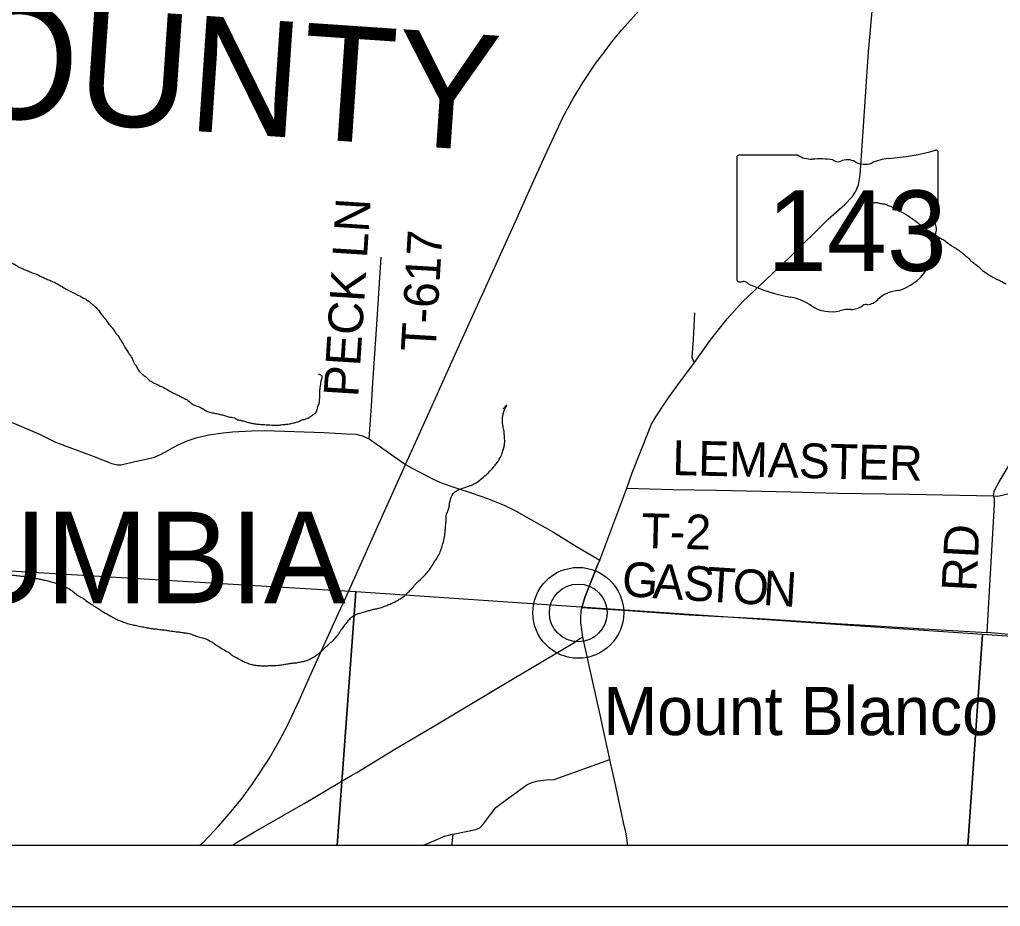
# Model space of a CAD drawing. Extents: x -8.2 to 34, y 0 to 22.
# Drawn here: x 5.685 to 7.291, y 14 to 15.452 of the extents above; entities that cross this region are included whole.
import ezdxf

# ---------------------------------------------------------------- set-up
doc = ezdxf.new("R2010")
doc.units = 0
for name, color, linetype in [('GM_X_Corporation', 7, 'Continuous'), ('GM_X_County_Road', 7, 'Continuous'), ('GM_X_County_Text', 7, 'Continuous'), ('GM_X_Minor_River', 7, 'Continuous'), ('GM_X_State_Location', 7, 'Continuous'), ('GM_X_State_Route', 7, 'Continuous'), ('GM_X_State_Shield', 7, 'Continuous'), ('GM_X_Township_Road', 7, 'Continuous'), ('GM_X_Township_Road_Text', 7, 'Continuous'), ('GM_X_Township_Text', 7, 'Continuous'), ('GM_X_Unincorporated', 7, 'Continuous'), ('GM_X_Unincorporated_Location', 7, 'Continuous'), ('GM_X_Unincorporated_Text', 7, 'Continuous'), ('SH_Data', 7, 'Continuous')]:
    doc.layers.add(name, color=color, linetype=linetype)

msp = doc.modelspace()

# ---------------------------------------------------------------- linework, layer by layer
at = {"layer": 'GM_X_Corporation'}
for points in [[(4.1481, 14.1), (8.9, 14.1), (8.9, 15.3663), (8.5054, 15.392), (7.8479, 15.4343), (7.082, 15.4841), (6.7558, 15.5053), (6.7389, 15.5064), (6.2987, 15.5287), (5.4088, 15.5882), (4.4836, 15.6492), (4.4152, 15.6505), (4.2922, 15.6569), (4.2674, 15.658), (4.2558, 15.6585), (4.2352, 15.4906), (4.2113, 15.0848), (4.1846, 14.6878), (4.1741, 14.5315), (4.1604, 14.3288)], [(5.1819, 14.1), (6.2054, 14.1), (6.2355, 14.5152), (5.2132, 14.576)], [(6.2054, 14.1), (7.2372, 14.1), (7.2616, 14.4454), (6.2355, 14.5152)], [(7.2372, 14.1), (8.2568, 14.1), (8.2775, 14.3753), (7.2616, 14.4454)]]:
    msp.add_lwpolyline(points, close=True, dxfattribs=at)
at = {"layer": 'GM_X_County_Road'}
for points in [[(6.07, 14.1219), (6.1511, 14.1686), (6.2289, 14.2147), (6.2374, 14.2194), (6.2996, 14.2572), (6.3617, 14.2938), (6.4745, 14.3616), (6.5914, 14.4312), (6.6022, 14.4388), (6.6074, 14.4407)], [(6.0341, 14.1), (6.0414, 14.1052), (6.0562, 14.1139), (6.07, 14.1219)]]:
    msp.add_lwpolyline(points, dxfattribs=at)
at = {"layer": 'GM_X_Minor_River'}
for points in [[(5.3703, 15.4396), (5.3769, 15.4348), (5.3824, 15.4281), (5.3879, 15.4211), (5.394, 15.4122), (5.398, 15.406), (5.4004, 15.399), (5.4032, 15.3913), (5.4052, 15.3841), (5.4062, 15.3772), (5.4088, 15.3649), (5.4108, 15.3573), (5.414, 15.3503), (5.4172, 15.3445), (5.4222, 15.3356), (5.4281, 15.3286), (5.4344, 15.3242), (5.4399, 15.3202), (5.4462, 15.3139), (5.4517, 15.3092), (5.4598, 15.3017), (5.4657, 15.2962), (5.4727, 15.2891), (5.4778, 15.2833), (5.4826, 15.277), (5.4873, 15.27), (5.4934, 15.26), (5.4977, 15.253), (5.5009, 15.2472), (5.5041, 15.2398), (5.5091, 15.2309), (5.5135, 15.2243), (5.52, 15.2158), (5.5236, 15.2096), (5.5291, 15.2033), (5.5357, 15.1974), (5.542, 15.1919), (5.5475, 15.1875), (5.5587, 15.1795), (5.5668, 15.1743), (5.5746, 15.168), (5.582, 15.1632), (5.5899, 15.1591), (5.5965, 15.1536), (5.6043, 15.1469), (5.6102, 15.1417), (5.6165, 15.137), (5.6234, 15.1299), (5.6293, 15.1236), (5.6344, 15.1178), (5.6373, 15.1116), (5.6374, 15.1047), (5.638, 15.099), (5.6443, 15.0844), (5.6487, 15.0774), (5.6515, 15.0712), (5.6555, 15.065), (5.6613, 15.0595), (5.6703, 15.0546), (5.677, 15.0514), (5.6833, 15.0474), (5.6931, 15.0429), (5.6987, 15.0408), (5.7058, 15.0375), (5.7133, 15.035), (5.7211, 15.0309), (5.7275, 15.0281), (5.7346, 15.0252), (5.7421, 15.0219), (5.7496, 15.0178), (5.7577, 15.013), (5.7659, 15.0085), (5.7745, 15.0041), (5.7809, 15.0008), (5.7865, 14.998), (5.7936, 14.994), (5.7991, 14.9904), (5.8061, 14.9844), (5.812, 14.9789), (5.8215, 14.9664), (5.8284, 14.9582), (5.8328, 14.952), (5.8386, 14.945), (5.8426, 14.9391), (5.847, 14.9333), (5.852, 14.9255), (5.8556, 14.9197), (5.8592, 14.9131), (5.8635, 14.9062), (5.8686, 14.8988), (5.8714, 14.8926), (5.8761, 14.8845), (5.88, 14.8779), (5.8859, 14.8716), (5.8918, 14.8669), (5.8988, 14.8606)], [(7.0807, 15.1515), (7.0868, 15.1524), (7.0944, 15.151), (7.1023, 15.1496), (7.1087, 15.1471), (7.1158, 15.1442), (7.1221, 15.1398), (7.1303, 15.1361), (7.137, 15.1325), (7.1452, 15.1269), (7.1522, 15.1217), (7.1626, 15.1138), (7.1715, 15.1074), (7.1801, 15.1022), (7.1882, 15.097), (7.1953, 15.0926), (7.2016, 15.0886), (7.2094, 15.0826), (7.2154, 15.079), (7.2213, 15.075), (7.2287, 15.0695), (7.2354, 15.0639), (7.2423, 15.0572), (7.249, 15.0521), (7.2546, 15.0477), (7.2616, 15.0414), (7.2679, 15.0366), (7.2746, 15.0326), (7.2824, 15.0278), (7.2884, 15.0253), (7.2943, 15.0221), (7.3003, 15.0188)], [(5.8988, 14.8606), (5.9059, 14.8569), (5.9156, 14.852), (5.9238, 14.8479), (5.9324, 14.8431), (5.9403, 14.839), (5.9459, 14.8362), (5.9533, 14.8325), (5.9608, 14.8285), (5.9663, 14.8237), (5.9742, 14.8197), (5.9809, 14.8172), (5.9865, 14.814), (5.9928, 14.8103), (6.0004, 14.8082), (6.006, 14.8072), (6.0143, 14.8054), (6.0207, 14.8037), (6.0271, 14.8016), (6.0369, 14.7998), (6.0425, 14.7969), (6.0481, 14.7956), (6.0542, 14.7939), (6.0613, 14.7921), (6.0673, 14.7908), (6.0734, 14.7898), (6.0825, 14.7891), (6.0912, 14.7885), (6.1067, 14.7879), (6.1136, 14.7885), (6.1212, 14.7894), (6.1281, 14.7903), (6.1353, 14.7919), (6.1422, 14.794), (6.148, 14.7965), (6.1541, 14.7981), (6.1603, 14.8014), (6.1661, 14.8053), (6.1716, 14.8109), (6.173, 14.8165), (6.1755, 14.8233), (6.1764, 14.8289), (6.1769, 14.8445), (6.1775, 14.8502), (6.1785, 14.8562), (6.1794, 14.8619), (6.1804, 14.8679), (6.1744, 14.8712)], [(6.4774, 14.7821), (6.4761, 14.789), (6.4756, 14.7951), (6.4758, 14.8008), (6.4771, 14.8064), (6.4792, 14.8136), (6.4829, 14.8203), (6.4766, 14.8148)], [(5.924, 14.4525), (5.9308, 14.4512), (5.9418, 14.4497), (5.9478, 14.4491), (5.9546, 14.4481), (5.9629, 14.4467), (5.9708, 14.4441), (5.9783, 14.4412), (5.9866, 14.4391), (5.9941, 14.4362), (6.0067, 14.4281), (6.0138, 14.4237), (6.022, 14.4189), (6.0287, 14.4149), (6.0346, 14.4105), (6.0413, 14.4069), (6.0506, 14.4016), (6.0574, 14.3987), (6.0649, 14.3962), (6.0705, 14.3949), (6.077, 14.3943), (6.083, 14.3937), (6.0895, 14.3939), (6.0971, 14.3944), (6.1081, 14.3948), (6.1176, 14.396), (6.1249, 14.3973), (6.131, 14.3982), (6.1367, 14.3988), (6.1443, 14.4), (6.1516, 14.4017), (6.1581, 14.4038), (6.1662, 14.408), (6.1736, 14.4131), (6.1795, 14.4182), (6.1873, 14.4256), (6.1944, 14.4318), (6.2014, 14.4384), (6.2074, 14.4462), (6.2113, 14.4518), (6.2161, 14.458), (6.2209, 14.4647), (6.2256, 14.4703), (6.2323, 14.4761), (6.2384, 14.479), (6.2461, 14.4814), (6.2534, 14.4834), (6.2595, 14.4851), (6.2664, 14.4868), (6.2729, 14.4881), (6.2829, 14.4915), (6.2898, 14.4943), (6.2971, 14.4975), (6.3037, 14.5011), (6.3099, 14.5047), (6.3169, 14.5102), (6.3228, 14.5157), (6.3283, 14.5216), (6.3346, 14.5286), (6.3436, 14.5374), (6.3495, 14.5433), (6.3551, 14.5499), (6.3606, 14.5581), (6.3666, 14.5674), (6.3719, 14.5763), (6.3756, 14.5853), (6.3782, 14.594), (6.3808, 14.6049), (6.3818, 14.6121), (6.3824, 14.6197), (6.383, 14.6269), (6.3837, 14.6337), (6.3835, 14.6401), (6.3856, 14.6458), (6.388, 14.6518), (6.389, 14.6586), (6.3904, 14.6654), (6.3925, 14.671), (6.3973, 14.6784), (6.4035, 14.682), (6.4127, 14.6855), (6.4204, 14.6879), (6.4265, 14.6904), (6.4343, 14.6947), (6.4425, 14.7012), (6.4511, 14.7085), (6.4569, 14.7144), (6.4637, 14.7226), (6.468, 14.7281), (6.4712, 14.7337), (6.4753, 14.7419), (6.4775, 14.7494), (6.4788, 14.7555), (6.4794, 14.7615), (6.4789, 14.7692), (6.4784, 14.7764), (6.4774, 14.7821)], [(5.1466, 14.5717), (5.1609, 14.5766), (5.1712, 14.577), (5.1807, 14.5774), (5.1872, 14.578), (5.1944, 14.5774), (5.2015, 14.5752), (5.2083, 14.5727), (5.2183, 14.5675), (5.2277, 14.5622), (5.2381, 14.5581), (5.2592, 14.5528), (5.269, 14.551), (5.2769, 14.5488), (5.2905, 14.5453), (5.298, 14.5435), (5.3078, 14.5417), (5.3154, 14.5399), (5.3236, 14.5374), (5.3319, 14.5352), (5.3394, 14.5331), (5.3481, 14.5305), (5.356, 14.5291), (5.3635, 14.5273), (5.3722, 14.5248), (5.3816, 14.5222), (5.3895, 14.5204), (5.397, 14.519), (5.4031, 14.518), (5.4133, 14.5166), (5.422, 14.5155), (5.4337, 14.5147), (5.4405, 14.5145), (5.4489, 14.5154), (5.4558, 14.5163), (5.4615, 14.5172), (5.4676, 14.5189), (5.4738, 14.5203), (5.4803, 14.5216), (5.4867, 14.5225), (5.4944, 14.5241), (5.5017, 14.5265), (5.5089, 14.5278), (5.5162, 14.5295), (5.5246, 14.5307), (5.533, 14.5312), (5.5421, 14.5309), (5.55, 14.5303), (5.5587, 14.5296), (5.569, 14.5296), (5.5789, 14.5304), (5.5892, 14.532), (5.5999, 14.5335), (5.6082, 14.5348), (5.6174, 14.5364), (5.63, 14.539), (5.6357, 14.54), (5.6449, 14.5415), (5.6544, 14.5424), (5.6628, 14.5432), (5.6704, 14.5426), (5.6791, 14.5419), (5.6878, 14.5409), (5.6938, 14.5403), (5.7006, 14.5393), (5.7063, 14.5384), (5.7127, 14.537), (5.7199, 14.5356), (5.7274, 14.5339), (5.7353, 14.5321), (5.7432, 14.5296), (5.7492, 14.5278), (5.7556, 14.5253), (5.7623, 14.5221), (5.7679, 14.5189), (5.7735, 14.5149), (5.7801, 14.5097), (5.7876, 14.5053), (5.7961, 14.4993), (5.8024, 14.4949), (5.8106, 14.4897), (5.8173, 14.4853), (5.8236, 14.4813), (5.8311, 14.4773), (5.8374, 14.4736), (5.8434, 14.4704), (5.8505, 14.4675), (5.8569, 14.465), (5.8666, 14.462), (5.8745, 14.4603), (5.8836, 14.4584), (5.8923, 14.4566), (5.9002, 14.4552), (5.9081, 14.4542), (5.9164, 14.4532), (5.924, 14.4525)]]:
    msp.add_spline(points, degree=3, dxfattribs=at)
at = {"layer": 'GM_X_State_Route'}
for points in [[(6.7476, 14.8327), (6.7629, 14.8542), (6.7898, 14.8906), (6.8166, 14.9279), (6.8432, 14.962), (6.8591, 14.9796), (6.8687, 14.9899), (6.9461, 15.0632), (7.0087, 15.1252), (7.0358, 15.1494), (7.0486, 15.1622), (7.0541, 15.1711), (7.0585, 15.1816), (7.0614, 15.1979), (7.0661, 15.269), (7.075, 15.3989), (7.0822, 15.4836)], [(5.9804, 14.1), (5.9868, 14.1059), (6.0116, 14.1319), (6.0284, 14.1515), (6.0478, 14.1752), (6.0665, 14.2006), (6.0945, 14.2428), (6.1109, 14.2714), (6.1231, 14.2951), (6.1436, 14.3382), (6.1599, 14.3752), (6.2073, 14.4799), (6.2193, 14.5057), (6.2529, 14.581), (6.2781, 14.637), (6.317, 14.7235), (6.3386, 14.7713), (6.4078, 14.9242), (6.4654, 15.0514), (6.4725, 15.0671), (6.497, 15.1215), (6.5242, 15.1825), (6.5487, 15.2367), (6.5758, 15.2938), (6.5915, 15.3226), (6.6079, 15.3497), (6.6281, 15.3803), (6.643, 15.3999), (6.6546, 15.4154), (6.671, 15.4354), (6.7039, 15.472)], [(6.6348, 14.5669), (6.6615, 14.6369), (6.679, 14.685), (6.6879, 14.71), (6.7154, 14.7784), (6.7197, 14.7893), (6.7267, 14.8015), (6.7424, 14.8253), (6.7476, 14.8327)], [(6.6057, 14.4896), (6.6111, 14.5072), (6.6325, 14.5615), (6.6348, 14.5669)], [(6.6801, 14.1), (6.6797, 14.1092), (6.6778, 14.1213), (6.6738, 14.1372), (6.6611, 14.1967), (6.6515, 14.2403), (6.6354, 14.3134), (6.6166, 14.3991), (6.6074, 14.4407), (6.6057, 14.4528), (6.6041, 14.465), (6.6041, 14.4748), (6.6043, 14.4822), (6.6057, 14.4896)]]:
    msp.add_lwpolyline(points, dxfattribs=at)
at = {"layer": 'GM_X_State_Shield'}
for p, q in [((7.1888, 15.1301), (7.1888, 15.2347)), ((6.8592, 15.2263), (6.8592, 15.0262)), ((6.959, 15.2298), (6.8625, 15.2298)), ((7.1888, 15.1301), (7.1888, 15.1301))]:
    msp.add_line(p, q, dxfattribs=at)
for centre, major_axis, start_param, end_param in [((7.0714, 15.5026), (0.3495, 0), 4.814394, 5.042369), ((7.1851, 15.2352), (0.00367, 0), 6.141152, 7.989035), ((6.863, 15.2268), (0.00382, 0), 1.712693, 3.28349), ((6.982, 15.253), (0.037, 0), 4.042523, 4.731795), ((6.9942, 15.1174), (0.133, 0), 1.404758, 1.657858), ((7.0244, 15.2278), (0.0107, 0), 3.836095, 5.185415), ((7.0401, 15.2047), (0.0222, 0), 0.950623, 2.079405), ((7.0688, 15.2364), (0.0267, 0), 4.081561, 5.145723), ((7.116, 15.1687), (0.0703, 0), 1.699011, 2.107814), ((7.188, 15.1224), (0.00568, 0), 1.883978, 3.671073), ((7.1849, 15.1297), (0.00393, 0), 5.05454, 6.418171), ((7.1518, 15.1091), (0.0341, 0), 5.934695, 6.695948), ((7.2019, 15.0862), (0.0248, 0), 2.387724, 3.262537), ((7.091, 15.0729), (0.0874, 0), 5.101752, 6.440018), ((6.863, 15.0258), (0.00385, 0), 3.00124, 4.508301), ((6.8636, 15.0463), (0.0294, 0), 4.665946, 4.897461), ((6.8696, 15.0147), (0.0106, 0), 0.519207, 1.627899), ((7.0034, 15.1945), (0.2524, 0), 4.195997, 4.488961), ((6.9282, 14.9363), (0.079, 0), 0.823519, 1.323587), ((7.0672, 15.0068), (0.0282, 0), 4.937069, 5.64225), ((7.1278, 14.97), (0.0479, 0), 1.647645, 2.488434), ((7.0136, 15.0137), (0.0501, 0), 4.026481, 4.996735), ((7.0426, 14.9445), (0.0412, 0), 1.495662, 1.94098), ((7.0462, 14.9987), (0.0267, 0), 4.691044, 5.507374), ((7.0704, 14.9793), (0.00752, 0), 1.147584, 2.315152)]:
    msp.add_ellipse(centre, major_axis=major_axis, ratio=0.8, start_param=start_param, end_param=end_param, dxfattribs=at)
at = {"layer": 'GM_X_Township_Road'}
msp.add_line((6.2573, 14.7654), (6.317, 14.7235), dxfattribs=at)
for points in [[(6.2573, 14.7654), (6.2616, 14.8192), (6.2637, 14.8573), (6.2702, 14.9529), (6.2769, 15.063)], [(6.7898, 14.8906), (6.7875, 14.8952), (6.7862, 14.8994), (6.7885, 14.9284), (6.7908, 14.9717)], [(5.6733, 14.7925), (5.7182, 14.7732), (5.744, 14.7598), (5.8058, 14.7371), (5.8364, 14.7249), (5.8454, 14.7231), (5.8516, 14.7229), (5.874, 14.7285), (5.8927, 14.732), (5.906, 14.7354), (5.9173, 14.7406), (5.9436, 14.7551), (5.9597, 14.762), (5.9759, 14.7677), (5.9953, 14.7719), (6.0187, 14.7755), (6.034, 14.7768), (6.0649, 14.7785), (6.0864, 14.7793), (6.1837, 14.7758), (6.2197, 14.7739), (6.236, 14.7729), (6.2419, 14.7717), (6.2464, 14.7705), (6.2501, 14.7688), (6.2573, 14.7654)], [(7.2792, 14.6724), (7.2862, 14.6714), (7.3117, 14.6775), (7.3412, 14.6846), (7.3507, 14.687), (7.3594, 14.6876), (7.3791, 14.6862), (7.3894, 14.686), (7.3967, 14.6864), (7.404, 14.6882), (7.4099, 14.691), (7.4202, 14.6961), (7.4479, 14.7122), (7.4852, 14.7337), (7.4989, 14.7425), (7.5078, 14.7465), (7.5172, 14.7494)], [(6.317, 14.7235), (6.328, 14.7177), (6.3624, 14.6995), (6.377, 14.6931), (6.3996, 14.6852), (6.426, 14.6763), (6.451, 14.6679), (6.4782, 14.6567), (6.5001, 14.646), (6.522, 14.6336), (6.5592, 14.6125), (6.5968, 14.5892), (6.6348, 14.5669)], [(7.2792, 14.6724), (7.2809, 14.6807), (7.2885, 14.6953), (7.3105, 14.7317)], [(6.6057, 14.4896), (6.6817, 14.4844), (6.7812, 14.4775), (6.8968, 14.4712), (7.022, 14.4633), (7.0692, 14.4604), (7.1653, 14.4542), (7.2692, 14.4482), (7.2741, 14.5354), (7.2812, 14.6579), (7.2812, 14.6671), (7.2792, 14.6724)], [(6.679, 14.685), (6.7547, 14.6828), (6.8261, 14.6816), (6.9481, 14.6789), (7.0241, 14.6763), (7.1415, 14.6748), (7.2516, 14.6728), (7.2792, 14.6724)], [(6.6348, 14.5669), (6.6325, 14.5615), (6.6111, 14.5072), (6.6057, 14.4896)], [(7.5005, 14.411), (7.4904, 14.4293), (7.4808, 14.4349), (7.4701, 14.4415), (7.4665, 14.4442), (7.4643, 14.4441), (7.4593, 14.4416), (7.4287, 14.4384), (7.3731, 14.4416), (7.3103, 14.4448), (7.2692, 14.4482)], [(6.3938, 14.118), (6.3948, 14.1182), (6.4323, 14.1258), (6.4385, 14.1287), (6.4446, 14.1353), (6.456, 14.1505), (6.4651, 14.1619), (6.4803, 14.1733), (6.5154, 14.1989), (6.5235, 14.2027), (6.5339, 14.2056), (6.5472, 14.207), (6.5605, 14.208), (6.6515, 14.2403)], [(6.3441, 14.1), (6.3492, 14.1016), (6.3663, 14.1082), (6.3801, 14.1149), (6.3881, 14.1168), (6.3938, 14.118)], [(6.3931, 14.1), (6.3934, 14.103), (6.3948, 14.1182)]]:
    msp.add_lwpolyline(points, dxfattribs=at)
at = {"layer": 'GM_X_Unincorporated'}
for radius in [0.0744, 0.0472]:
    msp.add_circle((6.5997, 14.4806), radius, dxfattribs=at)
at = {"layer": 'GM_X_Unincorporated_Location'}
msp.add_line((6.5997, 14.4806), (6.5997, 14.4806), dxfattribs=at)
at = {"layer": 'SH_Data'}
for p, q in [((4.1481, 14.1), (8.9, 14.1)), ((2, 14), (9, 14))]:
    msp.add_line(p, q, dxfattribs=at)

# ---------------------------------------------------------------- texts
at = {"layer": 'GM_X_County_Text'}
msp.add_text('MEIGS COUNTY', height=0.189394, rotation=356.1113, dxfattribs=at).set_placement((4.512, 15.3687))
at = {"layer": 'GM_X_State_Location'}
for s in ['s', 'r']:
    msp.add_text(s, height=0.000189, dxfattribs=at).set_placement((7.0203, 15.113))
msp.add_text('143', height=0.000189, rotation=0, dxfattribs=at).set_placement((6.9534, 15.0992))
at = {"layer": 'GM_X_State_Shield'}
msp.add_text('143', height=0.13184, dxfattribs=at).set_placement((6.9087, 15.0403))
at = {"layer": 'GM_X_Township_Road_Text'}
for s, height, rotation, p in [('PECK LN', 0.05682, 86.3714, (6.2395, 14.833)), ('T-617', 0.05682, 86.6338, (6.366, 14.907)), ('LEMASTER', 0.05682, 358.7066, (6.7533, 14.7063)), ('T-2', 0.05682, 358.5687, (6.7026, 14.587)), ('RD', 0.05682, 87.0658, (7.2511, 14.5146)), ('G', 0.0568, 355.6865, (6.6698, 14.5086)), ('A', 0.0568, 356.4682, (6.7205, 14.5048)), ('S', 0.0568, 356.4771, (6.7704, 14.5017)), ('T', 0.0568, 356.4815, (6.8087, 14.4993)), ('O', 0.0568, 356.4789, (6.8511, 14.4967)), ('N', 0.0568, 356.4814, (6.901, 14.4937))]:
    msp.add_text(s, height=height, rotation=rotation, dxfattribs=at).set_placement(p)
at = {"layer": 'GM_X_Township_Text'}
msp.add_text('COLUMBIA', height=0.15, rotation=0, dxfattribs=at).set_placement((5.1714, 14.4963))
at = {"layer": 'GM_X_Unincorporated_Text'}
msp.add_text('Mount Blanco', height=0.078977, rotation=0, dxfattribs=at).set_placement((6.6409, 14.2805))

doc.saveas('drawing.dxf')
